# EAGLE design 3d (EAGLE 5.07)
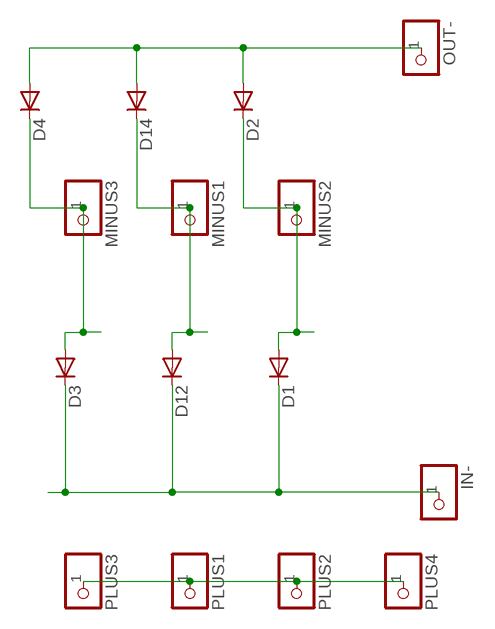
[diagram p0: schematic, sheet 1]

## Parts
D1  DIODE-SMC  [SMC]
D2  DIODE-SMC  [SMC]
D3  DIODE-SMC  [SMC]
D4  DIODE-SMC  [SMC]
D12  DIODE-SMC  [SMC]
D14  DIODE-SMC  [SMC]
IN-  PINHD-1X12MM0  [1X2MM0]
MINUS1  PINHD-1X12MM0  [1X2MM0]
MINUS2  PINHD-1X12MM0  [1X2MM0]
MINUS3  PINHD-1X12MM0  [1X2MM0]
OUT-  PINHD-1X12MM0  [1X2MM0]
PLUS1  PINHD-1X12MM0  [1X2MM0]
PLUS2  PINHD-1X12MM0  [1X2MM0]
PLUS3  PINHD-1X12MM0  [1X2MM0]
PLUS4  PINHD-1X12MM0  [1X2MM0]

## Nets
B1: D12.A D14.C MINUS1.1
B2: D1.A D2.C MINUS2.1
B3: D3.A D4.C MINUS3.1
GND: D2.A D4.A D14.A OUT-.1
IN-: D1.C D3.C D12.C IN-.1
PLUS: PLUS1.1 PLUS2.1 PLUS3.1 PLUS4.1

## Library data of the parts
D1-D4 D12 D14 = diode:DIODE-: DIODE
IN- MINUS1-MINUS3 OUT- PLUS1-PLUS4 = pinhead:PINHD-1X1: PIN HEADER

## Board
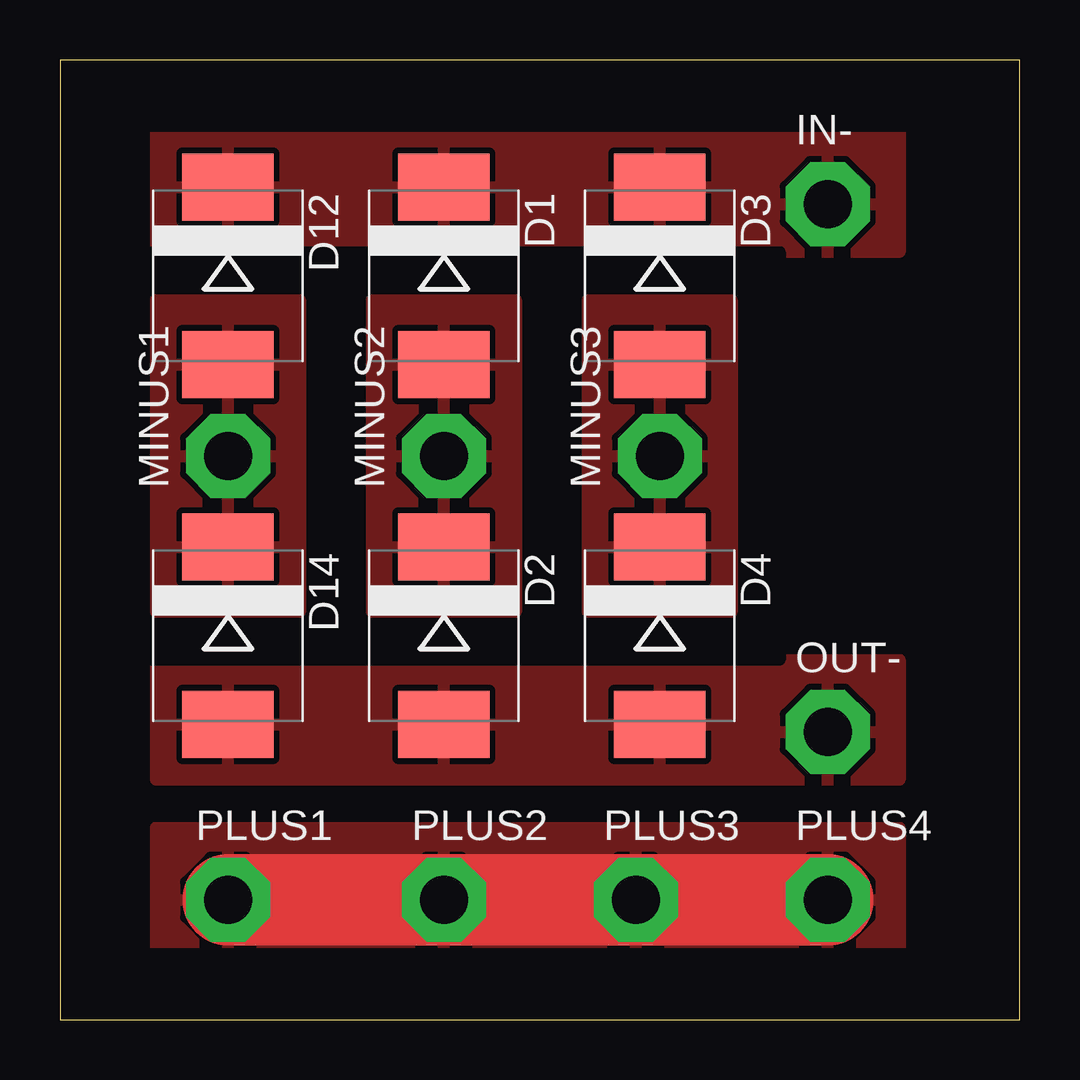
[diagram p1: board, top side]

Size 40 x 40 mm. Coordinates in mm from the lower left corner, seen from the top.
Outline: 0,0 40,0 40,40 0,40 0,0
Copper layers (1*16): Top 0.035mm / dielectric 1.5mm / Bottom 0.035mm
Design rules "default *": minimum track width 10mil, minimum drill 20mil, track to track 8mil, track to pad 8mil, pad to pad 8mil, via to via 8mil, smd to smd 8mil, copper to edge 3mm, drill to drill 8mil, minimum pad ring 1mil, minimum via ring 8mil, stop-mask expansion 4mil, vias tented up to drill 0mil, thermal gap 10mil

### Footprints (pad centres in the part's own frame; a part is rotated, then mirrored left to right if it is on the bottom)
SMC = smd 2.8 x 3.8: A 3.7,0; C -3.7,0
1X2MM0 = drill 2 pad 3.5 octagon: 1 0,0

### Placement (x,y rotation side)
D1  16,31 270 top
D2  16,16 270 top
D3  25,31 270 top
D4  25,16 270 top
D12  7,31 270 top
D14  7,16 270 top
IN-  32,34 0 top
MINUS1  7,23.5 90 top
MINUS2  16,23.5 90 top
MINUS3  25,23.5 90 top
OUT-  32,12 0 top
PLUS1  7,5 0 top
PLUS2  16,5 0 top
PLUS3  24,5 0 top
PLUS4  32,5 0 top

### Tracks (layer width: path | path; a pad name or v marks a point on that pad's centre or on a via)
B1
  pour Top: 4,30 10,30 10,17 4,17
B2
  pour Top: 13,30 19,30 19,17 13,17
B3
  pour Top: 22,30 28,30 28,17 22,17
GND
  pour Top (isolate 2, rank 2): 4,15 35,15 35,10 4,10
IN-
  pour Top (isolate 2, rank 2): 4,37 35,37 35,32 4,32
PLUS
  Top 3.81: PLUS1.1 PLUS2.1 PLUS3.1 PLUS4.1
  pour Top (isolate 2, rank 2): 4,7 4,8 35,8 35,3 4,3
